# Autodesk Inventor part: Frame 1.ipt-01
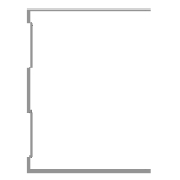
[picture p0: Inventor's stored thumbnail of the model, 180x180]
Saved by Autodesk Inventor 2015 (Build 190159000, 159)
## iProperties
Created: 2015-04
Part Number: Frame 1.ipt-01
Material: Aluminum 6061
Document SubType Name: Modeling
Standard: Unnamed
Designer: suporte
Language: en-US
Size Designation: (Unnamed 1)
Categories: <MemberInstance><Categories><Category DisplayName="Structural Shapes" InternalName="089c4875-fa83-4c05-b084-43b9cc11f5ed" Mnemonic="GRDR"><CategoryParameter Dis
Density: 2.7 g/cm^3
Appearance: Aluminum - Flat
IsCustomPart: 1
_CCFamilyMember: 1
_CCFamilyDisplayName: Frame 1
_FrameMemberDoc: Frame Member File
_Version: 15.0.0
_GetPNFromCC: 1
Author: suporte
G_L: 470,645 mm
G_W: 70,000 mm
G_H: 75,000 mm
+BD433694-75ED-40FA-B604-0D23CBD579F9+CUTDETAIL1: Miter 67,49 deg
+5C76CBEB-8B41-4733-85A3-2AE3D2FC03BA+CUTDETAIL2: Miter 67,51 deg
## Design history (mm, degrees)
node "Start Plane"
node "End Plane"
sketch "Sketch"
  geometry: L1 (34.6, 37.5)-(34.6, 36.7); L2 (34.6, 36.7)-(-34.6, 36.7); L3 (-34.6, -36.7)-(34.6, -36.7); L4 (34.6, -36.7)-(34.6, -37.5); L5 (34.6, -37.5)-(-35.4, -37.5); L6 (-35.4, 37.5)-(34.6, 37.5); L7 (-34.6, 36.7)-(-34.6, 31.7); L8 (-34.6, 31.7)-(-33.4, 30.5); L9 (-33.4, 30.5)-(-33.4, 10.746); L10 (-33.4, 10.746)-(-34.6, 9.546); L11 (-34.6, 9.546)-(-34.6, -9.546); L12 (-34.6, -9.546)-(-33.4, -10.746); L13 (-33.4, -10.746)-(-33.4, -30.5); L14 (-33.4, -30.5)-(-34.6, -31.7); L15 (-34.6, -31.7)-(-34.6, -36.7); L16 (-35.4, -37.5)-(-35.4, -31.369); L17 (-35.4, -31.369)-(-34.2, -30.169); L18 (-34.2, -30.169)-(-34.2, -11.077); L19 (-34.2, -11.077)-(-35.4, -9.877); L20 (-35.4, -9.877)-(-35.4, 9.877); L21 (-35.4, 9.877)-(-34.2, 11.077); L22 (-34.2, 11.077)-(-34.2, 30.169); L23 (-34.2, 30.169)-(-35.4, 31.369); L24 (-35.4, 31.369)-(-35.4, 37.5); L25 (-35.4, 0)-(30.37, 0); 3 further points
  constraints: 50 end point, 10 point on line, 9 parallel, 5 perpendicular, 4 equal length, 3 midpoint, 3 vertical, 2 vertical alignment, 1 collinear, 1 horizontal, 1 horizontal alignment
  dimensions: "d3" = 0.8 distance of L1.start L1.end; "d5" = 75 distance between parallel lines of L5 L6; "d6" = 0.8 distance between parallel lines of L24 L7; "d7" = 0.8 distance between parallel lines of L8 L23; "d8" = 0.8 distance between parallel lines of L22 L9; "d9" = 0.8 distance between parallel lines of L17 L14; "d10" = 0.8 distance between parallel lines of L13 L18; "d11" = 0.8 distance between parallel lines of L12 L19; "d12" = 0.8 distance between parallel lines of L21 L10; "d13" = 5 distance of L2.end L7.end; "d15" = 135 deg angle of L9 L8; "d16" = 2 distance between parallel lines of L24 L9; "d17" = 70 distance of L6.start L1.start
extrude "Body" join sketch "Sketch" stored distance "d24" = 0.13; taper "d25" = 0 deg
node "Driven Length"
  sketch "Sketch8"
    geometry: L1 (0, 0)-(10, 0) reference
    constraints: 2 end point, 1 horizontal
  workplane "Work Plane6"
  sketch "Sketch9"
    geometry: L1 (-2, 5.175)-(12, 5.175) reference; L2 (-2, 475.82)-(12, 475.82) reference
    dimensions: "d27" = 470.64466 distance between parallel lines of L1 L2 (derived)
workplane "Work Plane7"
split "Split1"
workplane "Work Plane8"
split "Split2"
body "Solid1"
other parameters: "tamanho" = 481, "G_OFFSET_START" = -5.17512 [user parameter; used in 1 equation term], "G_OFFSET_END" = -5.18022 [user parameter; used in 1 equation term], "d22" = 5.17512 (= -G_OFFSET_START), "d23" = 475.81978 (= tamanho + G_OFFSET_END), "G_L" = 470.64466 (= d27) [user parameter], "d32" = 90 deg
